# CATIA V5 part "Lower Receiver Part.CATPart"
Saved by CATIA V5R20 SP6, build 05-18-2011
Part number: Lower Receiver Part
Bounding box of the stored display mesh (mm): x -116 to 116, y -29.997 to 29.997, z -57.169 to -14
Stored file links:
  E:\LCS\20170920\#01 CATIA Lecture Materials\#55 GSD18\#01 CATPart\Lower Receiver Part.CATPart
  E:\LCS\20170920\#01 CATIA Lecture Materials\#55 GSD18\#01 CATPart\Receiver Assembly.CATProduct
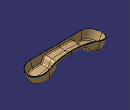
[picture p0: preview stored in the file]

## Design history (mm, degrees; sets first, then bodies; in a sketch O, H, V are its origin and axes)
Set1
  DatumCurve1 "Middle Boundary Curve": linked copy from another document
  DatumCurve2 "Lower Boundary Curve": linked copy from another document
  DatumCurve3 "Lower Guide Curve": linked copy from another document
  DatumCurve4 "Upper Boundary Curve": linked copy from another document
  DatumCurve5 "Upper Guide Curve": linked copy from another document
Set2 "Surface Data"
  Set3 "Cavity Body"
    Sweep1 "Parting Surface": type Segment, GuideCrv DatumCurve1, Length1 60, Length2 0, Angle 0, DraftDirection zx-plane
    Sweep2 "Side Surface": type Segment, GuideCrv DatumCurve3, GuideSurf Sweep1, Length1 40, Length2 5, Angle 95
    Sweep3 "Bottom Surface": type Segment, GuideCrv DatumCurve2, Length1 50, Length2 0, Angle 0, DraftDirection zx-plane
    Fillet1: type BiTangent, Element1 Sweep2, Element2 Sweep3, Radius 5
    Split1: ToCut Fillet1, Cutting yz-plane
    Symmetry1: Reference zx-plane, ToTransfor Split1
    Join1: Elements (Symmetry1; Split1)
    Symmetry2: Reference yz-plane, ToTransfor Join1
  Join2 "Cavity Final Surface": Elements (Join1; Symmetry2)
  Set4 "Core Body"
    Offset1: Offset Sweep1, Length -1
    Offset2: Offset Fillet1, Length -2
    CurvePar1: Offset DatumCurve4, Offset2 0, Offset1 100
    Sweep4 "Top Surface": type Circle, Guide CurvePar1, Radius 20, Angle1 0, Angle2 45, Reference DatumCurve4
    Project1 "Side Surface Guide Curve 01": ToProject DatumCurve5, Support Sweep4, Direction xy-plane
    Sweep5 "Side Surface": type Conic, Guide ({sweepconicextendedguide Guide Project1, Reference Sweep4, Angle 0}; {sweepconicextendedguide Guide DatumCurve3, Reference xy-plane, Angle 92}), Parameter 0.6
    Offset3: Offset Sweep5, Length 1
    Trim1: Trimmed (Sweep1; Offset3; Offset1; Offset2)
    Split2: ToCut Trim1, Cutting yz-plane
    Symmetry3: Reference zx-plane, ToTransfor Split2
    Join3: Elements (Split2; Symmetry3)
    Symmetry4: Reference yz-plane, ToTransfor Join3
  Join4 "Core Final Surface": Elements (Join3; Symmetry4)
  Trim2 "Lower Final Surface": Trimmed (Join2; Join4)
Body1 (main body)
Body2 "Lower Part"
  CloseSurface1: CloseElement Trim2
